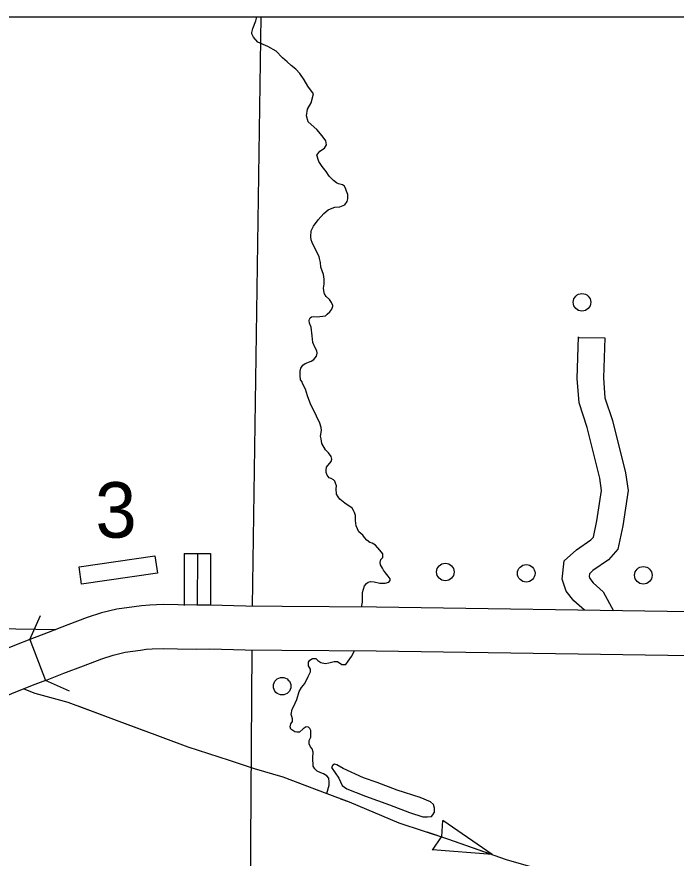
# Model space of a CAD drawing. Extents: x 1369979 to 1371646, y 379997 to 381064.
# Drawn here: x 1370780.4 to 1370824.5, y 380530.6 to 380586.9 of the extents above; entities that cross this region are included whole.
import ezdxf

# ---------------------------------------------------------------- set-up
doc = ezdxf.new("R2010")
doc.units = 0
doc.layers.add('R_Border Notes', color=7, linetype='Continuous')
doc.layers.add('R_No Plot', color=7, linetype='Continuous')

msp = doc.modelspace()

# ---------------------------------------------------------------- linework, layer by layer
at = {"layer": 'R_Border Notes'}
for p, q in [((1370791.552, 380550.985), (1370793.31, 380550.978)), ((1370808.815, 380533.132), (1370808.756, 380532.064)), ((1370812.158, 380530.863), (1370808.843, 380533.14)), ((1370808.166, 380531.154), (1370808.752, 380532.05)), ((1370812.158, 380530.863), (1370808.149, 380531.177))]:
    msp.add_line(p, q, dxfattribs=at)
for points in [[(1370796.062, 380585.81), (1370796.148, 380586.092), (1370796.335, 380586.597), (1370796.396, 380586.867)], [(1370796.681, 380586.867), (1370796.101, 380547.472)], [(1370800.193, 380581.726), (1370799.819, 380582.236), (1370799.574, 380582.654), (1370799.287, 380583.072), (1370799.013, 380583.36), (1370798.696, 380583.62), (1370798.437, 380583.85), (1370798.12, 380584.124), (1370797.689, 380584.571), (1370797.141, 380584.873), (1370796.479, 380585.176), (1370796.191, 380585.507), (1370796.076, 380585.723), (1370796.062, 380585.81)], [(1370800.413, 380577.63), (1370800.625, 380577.893), (1370800.928, 380578.095), (1370801.057, 380578.311), (1370801.014, 380578.57), (1370800.769, 380578.902), (1370800.424, 380579.334), (1370799.848, 380579.853), (1370799.733, 380580.242), (1370799.79, 380580.703), (1370800.05, 380581.121), (1370800.193, 380581.726)], [(1370802.133, 380575.645), (1370801.86, 380575.692), (1370801.737, 380575.779), (1370801.536, 380575.923), (1370801.241, 380576.218), (1370801.054, 380576.528), (1370800.78, 380576.866), (1370800.55, 380577.191), (1370800.413, 380577.63)], [(1370800.024, 380572.157), (1370800.046, 380572.562), (1370800.197, 380572.864), (1370800.507, 380573.289), (1370800.895, 380573.722), (1370801.183, 380573.974), (1370801.334, 380574.039), (1370801.622, 380574.139), (1370801.953, 380574.161), (1370802.285, 380574.305), (1370802.443, 380574.514), (1370802.486, 380574.701), (1370802.493, 380574.99), (1370802.4, 380575.206), (1370802.364, 380575.35), (1370802.263, 380575.552), (1370802.133, 380575.645)], [(1370801.262, 380567.96), (1370801.039, 380568.18), (1370800.924, 380568.338), (1370800.91, 380568.417), (1370800.874, 380568.72), (1370800.91, 380568.994), (1370800.91, 380569.332), (1370800.867, 380569.649), (1370800.694, 380570.125), (1370800.665, 380570.449), (1370800.607, 380570.716), (1370800.586, 380570.817), (1370800.384, 380571.249), (1370800.24, 380571.494), (1370800.096, 380571.775), (1370800.032, 380571.955), (1370800.024, 380572.157)], [(1370800.046, 380566.123), (1370799.924, 380566.382), (1370799.909, 380566.555), (1370799.931, 380566.656), (1370799.967, 380566.742), (1370800.068, 380566.821), (1370800.212, 380566.836), (1370800.435, 380566.8), (1370800.989, 380566.872), (1370801.111, 380566.98), (1370801.284, 380567.153), (1370801.421, 380567.333), (1370801.486, 380567.52), (1370801.486, 380567.571), (1370801.399, 380567.765), (1370801.262, 380567.96)], [(1370799.636, 380563.691), (1370800.032, 380563.857), (1370800.212, 380563.95), (1370800.392, 380564.174), (1370800.442, 380564.383), (1370800.42, 380564.541), (1370800.298, 380564.743), (1370800.147, 380565.096), (1370800.104, 380565.543), (1370800.046, 380566.123)], [(1370818.322, 380547.195), (1370817.611, 380547.818), (1370817.103, 380548.472), (1370816.838, 380549.267), (1370816.974, 380550.494), (1370817.785, 380551.224), (1370818.757, 380551.898), (1370818.925, 380552.088), (1370819.157, 380553.167), (1370819.471, 380555.195), (1370819.342, 380556.036), (1370818.501, 380559.404), (1370817.956, 380561.065), (1370817.842, 380562.688), (1370817.921, 380565.466)], [(1370817.966, 380565.43), (1370819.678, 380565.416), (1370819.601, 380562.725), (1370819.694, 380561.406), (1370820.191, 380559.891), (1370821.067, 380556.383), (1370821.25, 380555.194), (1370820.887, 380552.847), (1370820.547, 380551.27), (1370819.934, 380550.575), (1370818.878, 380549.843), (1370818.648, 380549.635), (1370818.628, 380549.456), (1370818.675, 380549.313), (1370818.896, 380549.03), (1370819.575, 380548.434), (1370820.262, 380547.166)], [(1370799.463, 380562.365), (1370799.427, 380562.466), (1370799.326, 380562.61), (1370799.305, 380562.898), (1370799.312, 380563.187), (1370799.355, 380563.381), (1370799.485, 380563.576), (1370799.636, 380563.691)], [(1370800.665, 380558.837), (1370800.737, 380559.215), (1370800.708, 380559.417), (1370800.629, 380559.698), (1370800.406, 380560.174), (1370800.14, 380560.721), (1370800.01, 380560.937), (1370799.801, 380561.521), (1370799.672, 380561.968), (1370799.463, 380562.365)], [(1370801.068, 380556.765), (1370801.385, 380557.137), (1370801.428, 380557.295), (1370801.385, 380557.482), (1370801.191, 380557.727), (1370800.989, 380557.929), (1370800.751, 380558.34), (1370800.708, 380558.664), (1370800.665, 380558.837)], [(1370802.774, 380554.018), (1370802.285, 380554.358), (1370801.968, 380554.632), (1370801.838, 380554.776), (1370801.738, 380554.964), (1370801.709, 380555.31), (1370801.73, 380555.511), (1370801.666, 380555.691), (1370801.615, 380555.828), (1370801.529, 380555.908), (1370801.378, 380555.994), (1370801.234, 380556.037), (1370801.111, 380556.225), (1370801.054, 380556.405), (1370801.047, 380556.563), (1370801.068, 380556.765)], [(1370804.653, 380550.379), (1370804.71, 380550.588), (1370804.826, 380550.732), (1370804.833, 380550.963), (1370804.638, 380551.215), (1370804.336, 380551.539), (1370804.127, 380551.683), (1370803.969, 380551.734), (1370803.76, 380551.885), (1370803.616, 380552.058), (1370803.487, 380552.209), (1370803.235, 380552.433), (1370803.04, 380552.829), (1370803.012, 380553.189), (1370803.012, 380553.528), (1370802.932, 380553.729), (1370802.882, 380553.874), (1370802.774, 380554.018)], [(1370791.552, 380550.985), (1370791.539, 380547.52)], [(1370792.431, 380550.981), (1370792.418, 380547.516)], [(1370793.31, 380550.978), (1370793.297, 380547.513)], [(1370803.414, 380547.411), (1370803.472, 380547.726), (1370803.48, 380548.374), (1370803.616, 380548.835), (1370803.739, 380548.979), (1370803.861, 380549.073), (1370804.005, 380549.116), (1370804.25, 380549.095), (1370804.631, 380549.015), (1370804.998, 380549.008), (1370805.229, 380549.066), (1370805.322, 380549.195), (1370805.329, 380549.296), (1370805.2, 380549.476), (1370805.006, 380549.7), (1370804.883, 380549.865), (1370804.804, 380550.017), (1370804.682, 380550.235), (1370804.653, 380550.379)], [(1370832.196, 380548.879), (1370831.723, 380548.385), (1370831.267, 380548.016), (1370831.041, 380547.907), (1370830.432, 380547.695), (1370830.26, 380547.644), (1370829.422, 380547.474), (1370828.415, 380547.308), (1370827.702, 380547.208), (1370826.8, 380547.15), (1370825.351, 380547.09), (1370804.417, 380547.403), (1370798.102, 380547.451)], [(1370798.107, 380547.451), (1370795.67, 380547.476), (1370793.279, 380547.539), (1370792.394, 380547.524), (1370791.152, 380547.555), (1370790.132, 380547.571), (1370789.257, 380547.537), (1370788.695, 380547.501), (1370788.198, 380547.43), (1370787.049, 380547.263), (1370786.008, 380547.016), (1370785.067, 380546.72), (1370783.753, 380546.216), (1370782.45, 380545.714), (1370781.215, 380545.241)], [(1370781.215, 380545.241), (1370781.931, 380546.847)], [(1370798.08, 380544.521), (1370804.385, 380544.474), (1370825.39, 380544.159), (1370826.955, 380544.224), (1370828, 380544.292), (1370828.856, 380544.412), (1370829.952, 380544.592), (1370830.967, 380544.799), (1370831.328, 380544.905), (1370832.163, 380545.196), (1370832.847, 380545.526), (1370833.71, 380546.225), (1370834.311, 380546.853)], [(1370760.147, 380546.287), (1370782.962, 380545.911)], [(1370781.215, 380545.241), (1370780.306, 380544.893), (1370777.468, 380543.75), (1370776.69, 380543.415), (1370775.924, 380543.136), (1370775.594, 380543.046)], [(1370781.215, 380545.241), (1370782.264, 380542.506)], [(1370782.264, 380542.506), (1370783.501, 380542.979), (1370784.804, 380543.482), (1370786.032, 380543.952), (1370786.787, 380544.19), (1370787.599, 380544.383), (1370788.615, 380544.53), (1370788.997, 380544.585), (1370789.408, 380544.611), (1370790.165, 380544.64), (1370791.092, 380544.625), (1370792.383, 380544.594), (1370793.265, 380544.609), (1370795.615, 380544.547), (1370798.076, 380544.521)], [(1370796.067, 380544.542), (1370795.88, 380515.497), (1370795.4, 380483.569)], [(1370800.003, 380543.247), (1370799.859, 380543.485), (1370799.866, 380543.723), (1370799.953, 380543.867), (1370800.132, 380543.96), (1370800.356, 380543.96), (1370800.478, 380543.838), (1370800.694, 380543.701), (1370800.967, 380543.643), (1370801.219, 380543.679), (1370801.586, 380543.78), (1370801.81, 380543.773), (1370802.09, 380543.564), (1370802.364, 380543.579), (1370802.522, 380543.788), (1370802.738, 380544.097), (1370802.929, 380544.485)], [(1370798.861, 380540.749), (1370799.089, 380541.218), (1370799.233, 380541.766), (1370799.384, 380542.032), (1370799.607, 380542.292), (1370799.845, 380542.762), (1370800.003, 380543.089), (1370800.003, 380543.247)], [(1370782.264, 380542.506), (1370781.377, 380542.166), (1370778.596, 380541.046), (1370777.772, 380540.691), (1370776.812, 380540.341), (1370776.364, 380540.219)], [(1370783.869, 380541.79), (1370782.264, 380542.506)], [(1370780.821, 380541.942), (1370781.561, 380541.659), (1370783.759, 380541.058)], [(1370780.821, 380541.942), (1370781.561, 380541.659), (1370783.035, 380541.256)], [(1370783.759, 380541.058), (1370786.996, 380539.845), (1370789.757, 380538.824)], [(1370784.505, 380540.778), (1370786.996, 380539.845), (1370788.853, 380539.158)], [(1370800.183, 380537.717), (1370800.118, 380537.921), (1370799.996, 380538.058), (1370799.902, 380538.26), (1370799.917, 380538.483), (1370800.017, 380538.707), (1370800.025, 380538.966), (1370800.017, 380539.146), (1370799.96, 380539.29), (1370799.852, 380539.384), (1370799.701, 380539.391), (1370799.513, 380539.261), (1370799.269, 380539.038), (1370799.082, 380539.038), (1370798.938, 380539.074), (1370798.686, 380539.24), (1370798.635, 380539.398), (1370798.691, 380539.6), (1370798.786, 380539.766), (1370798.786, 380539.931), (1370798.736, 380540.097), (1370798.7, 380540.227), (1370798.772, 380540.587), (1370798.861, 380540.749)], [(1370789.757, 380538.824), (1370791.782, 380538.069), (1370794.561, 380537.167), (1370796.232, 380536.619), (1370798.153, 380536.057), (1370801.083, 380534.944)], [(1370790.304, 380538.62), (1370791.782, 380538.069), (1370794.561, 380537.167), (1370794.695, 380537.123)], [(1370801.083, 380534.944), (1370801.234, 380535.491), (1370801.241, 380535.707), (1370801.212, 380535.974), (1370801.09, 380536.125), (1370800.867, 380536.262), (1370800.687, 380536.32), (1370800.435, 380536.428), (1370800.291, 380536.601), (1370800.176, 380536.781), (1370800.154, 380537.328), (1370800.183, 380537.717)], [(1370802.422, 380535.253), (1370803.674, 380534.771), (1370805.272, 380534.194), (1370806.618, 380533.683), (1370807.511, 380533.395), (1370807.813, 380533.395), (1370808.079, 380533.416), (1370808.187, 380533.524), (1370808.288, 380533.69), (1370808.295, 380533.971), (1370808.216, 380534.201), (1370808.022, 380534.389), (1370807.331, 380534.677), (1370805.797, 380535.16), (1370804.451, 380535.678), (1370803.544, 380535.988), (1370802.191, 380536.615), (1370801.766, 380536.86), (1370801.594, 380536.91), (1370801.479, 380536.838), (1370801.407, 380536.68), (1370801.644, 380536.327), (1370801.882, 380535.959), (1370802.119, 380535.477)], [(1370796.165, 380536.641), (1370796.232, 380536.619), (1370798.153, 380536.057), (1370800.554, 380535.145)], [(1370802.119, 380535.477), (1370802.422, 380535.253)], [(1370801.083, 380534.944), (1370802.583, 380534.379), (1370805.909, 380532.989), (1370809.161, 380531.923), (1370813.093, 380530.533), (1370815.171, 380529.931)], [(1370802.001, 380534.598), (1370802.583, 380534.379), (1370805.909, 380532.989), (1370806.302, 380532.86)], [(1370807.772, 380532.378), (1370809.161, 380531.923), (1370812.158, 380530.863)]]:
    msp.add_lwpolyline(points, dxfattribs=at)
msp.add_lwpolyline([(1370789.592, 380550.841), (1370789.761, 380549.681), (1370784.688, 380548.941), (1370784.519, 380550.1)], close=True, dxfattribs=at)
for centre in [(1370818.155, 380567.785), (1370809.01, 380549.756), (1370814.427, 380549.664), (1370822.255, 380549.534), (1370798.096, 380542.116)]:
    msp.add_circle(centre, 0.586, dxfattribs=at)
at = {"layer": 'R_No Plot'}
msp.add_lwpolyline([(1370544.495, 380586.867), (1371140.383, 380586.867), (1371140.383, 380146.391), (1370544.495, 380146.391)], close=True, dxfattribs=at)

# ---------------------------------------------------------------- texts
at = {"layer": 'R_Border Notes'}
msp.add_text('3', height=3.712, rotation=1.0819, dxfattribs=at).set_placement((1370785.63, 380552.02))

doc.saveas('drawing.dxf')
